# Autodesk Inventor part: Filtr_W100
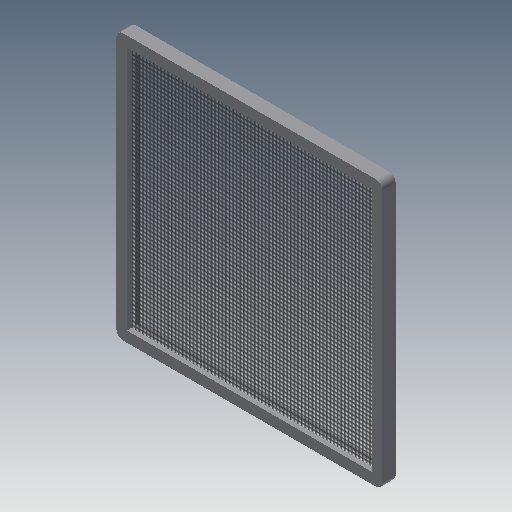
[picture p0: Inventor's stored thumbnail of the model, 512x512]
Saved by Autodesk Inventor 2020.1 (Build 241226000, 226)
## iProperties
Created: 2005-10
Part Number: Filtr_W100
Document SubType Name: Modeling
Designer: F.Stasiak
Density: 1 g/cm^3
Material: Ogólny
Appearance: Domyślna
Manager: www.cadconsulting.pl
Company: Fabian Stasiak CAD Consulting
Author: F.Stasiak
Subject: Zbiór ćwiczeń. Autodesk Inventor 2020. Kurs podstawowy
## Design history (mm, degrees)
sketch "Szkic1"
  geometry: L1 (216, 101)-(26, 101) reference; L2 (21, 96)-(21, -94) reference; L3 (26, -99)-(216, -99) reference; L4 (221, -94)-(221, 96) reference; L5 (217, 96)-(217, -94) reference; L6 (216, -95)-(26, -95) reference; L7 (25, -94)-(25, 96) reference; L8 (26, 97)-(216, 97) reference; L9 (29, 93)-(213, 93); L10 (213, 93)-(213, -91); L11 (213, -91)-(29, -91); L12 (29, -91)-(29, 93); A1 r 5 centre (216, 96) between (221, 96) and (216, 101) reference; A2 r 5 centre (26, 96) between (26, 101) and (21, 96) reference; A3 r 5 centre (26, -94) between (21, -94) and (26, -99) reference; A4 r 5 centre (216, -94) between (216, -99) and (221, -94) reference; A5 r 1 centre (216, -94) between (216, -95) and (217, -94) reference; A6 r 1 centre (26, -94) between (25, -94) and (26, -95) reference; A7 r 1 centre (26, 96) between (26, 97) and (25, 96) reference; A8 r 1 centre (216, 96) between (217, 96) and (216, 97) reference
  constraints: 8 end point, 2 parallel, 1 horizontal, 1 perpendicular
  dimensions: "d0" = 8 distance between parallel lines of L1 L9; "d1" = 8 distance between parallel lines of L2 L12; "d2" = 8 distance between parallel lines of L3 L11; "d3" = 8 distance between parallel lines of L4 L10
extrude "Wyciągnięcie proste1" new body sketch "Szkic1" stored distance "d4" = 10; taper "d5" = 0 deg
sketch "Szkic2"
  geometry: L1 (213, 93)-(213, -91) reference; L2 (213, -91)-(29, -91) reference; L3 (29, -91)-(29, 93) reference; L4 (29, 93)-(213, 93) reference
extrude "Wyciągnięcie proste2" join sketch "Szkic2" stored distance "d6" = 3; taper "d7" = 0 deg
node "Bryła1"
node "Korpusy bryłowe"
node "Korpusy powierzchniowe"
node "Odniesienie1"
